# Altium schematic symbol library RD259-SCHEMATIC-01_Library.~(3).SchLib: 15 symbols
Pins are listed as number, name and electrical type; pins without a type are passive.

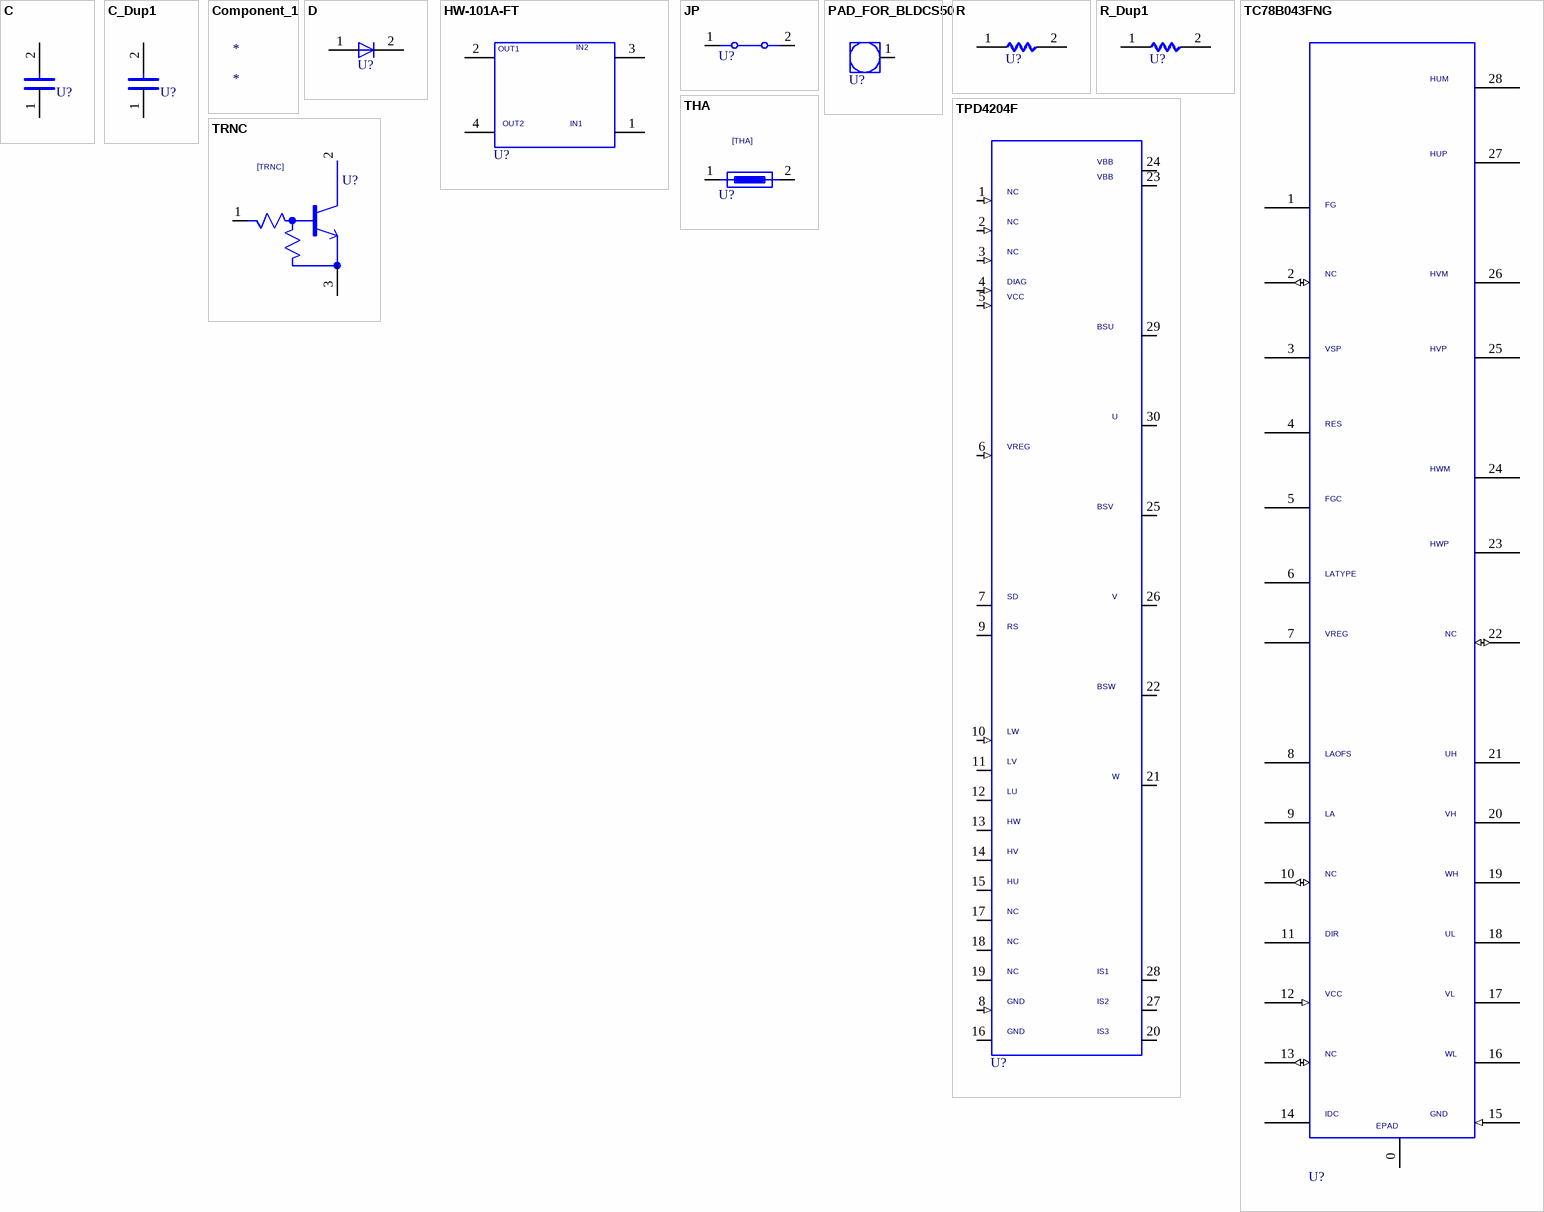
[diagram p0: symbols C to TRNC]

## C
designator U?  (value not drawn)
OriginalSymbolOrigin: (2540,7620); Altium-Right: 20; Altium-Bottom: 10
pins: 1, 2

## C_Dup1
designator U?, comment C  (value not drawn)
OriginalSymbolOrigin: (2540,7620); Altium-Right: 20; Altium-Bottom: 10
pins: 1, 2

## Component_1
designator *

## D
designator U?  (value not drawn)
SAVEAREA0: -225,-91,12804,7836; SAVECOUNT: 3; TIME: 14:49:55; UPDATEUSER: 19870035; UPDATETIME: 14:20:16; OriginalSymbolOrigin: (5080,5080); Altium-Right: 10; Altium-Bottom: 20
pins: 1 A, 2 C

## HW-101A-FT
designator U?  (value not drawn)
SAVEAREA0: -12224,-318,37706,25614; TIME: 11:47:14; UPDATEUSER: t5459927; UPDATETIME: 12:34:57; SAVECOUNT: 11; OriginalSymbolOrigin: (5080,17780); Altium-Right: 80; Altium-Bottom: 70
pins: 1, 2, 3, 4

## JP
designator U?  (value not drawn)
OriginalSymbolOrigin: (2540,5080); Altium-Right: 40; Altium-Bottom: 20
pins: 1, 2

## PAD_FOR_BLDCS50
designator U?  (value not drawn)
SAVEAREA0: -12224,-318,37706,25614; TIME: 11:47:14; UPDATEUSER: t5459927; UPDATETIME: 16:31:56; SAVECOUNT: 8; OriginalSymbolOrigin: (7620,17780); Altium-Right: 20
pins: 1

## R
designator U?  (value not drawn)
OriginalSymbolOrigin: (5080,5080); Altium-Right: 20
pins: 1, 2

## R_Dup1
designator U?, comment R  (value not drawn)
OriginalSymbolOrigin: (5080,5080); Altium-Right: 20
pins: 1, 2

## TC78B043FNG
designator U?  (value not drawn)
SAVEAREA0: -18325,-397,56528,38480; SAVECOUNT: 26; TIME: 12:23:18; UPDATEUSER: t5459927; UPDATETIME: 08:57:33; OriginalSymbolOrigin: (7620,190500); Altium-Right: 110; Altium-Bottom: 730
pins: 0, 1, 2 (io), 3, 4, 5, 6, 7, 8, 9, 10 (io), 11, 12 (in), 13 (io), 14, 15 (in), 16, 17, 18, 19, 20, 21, 22 (io), 23, 24, 25, 26, 27, 28

## THA
designator U?  (value not drawn)
SAVECOUNT: 3; SAVEAREA0: -562,-143,15615,10489; TIME: 16:37:29; UPDATEUSER: sato-yr; OriginalSymbolOrigin: (2540,5080); Altium-Right: 40; Altium-Bottom: 20
pins: 1, 2

## TPD4204F
designator U?  (value not drawn)
TIME: 16:32:01; UPDATEUSER: t5459927; UPDATETIME: 11:42:20; SAVECOUNT: 10; SAVEAREA0: -38352,-57023,57455,-16941; OriginalSymbolOrigin: (2540,154940); Altium-Right: 100; Altium-Bottom: 610
pins: 1 (in), 2 (in), 3 (in), 4 (in), 5 (in), 6 (in), 7, 8 (in), 9, 10 (in), 11, 12, 13, 14, 15, 16, 17, 18, 19, 20, 21, 22, 23, 24, 25, 26, 27, 28, 29, 30

## TRNC
designator U?  (value not drawn)
OriginalSymbolOrigin: (2540,22860); Altium-Right: 70
pins: 1 B, 2 C, 3 E

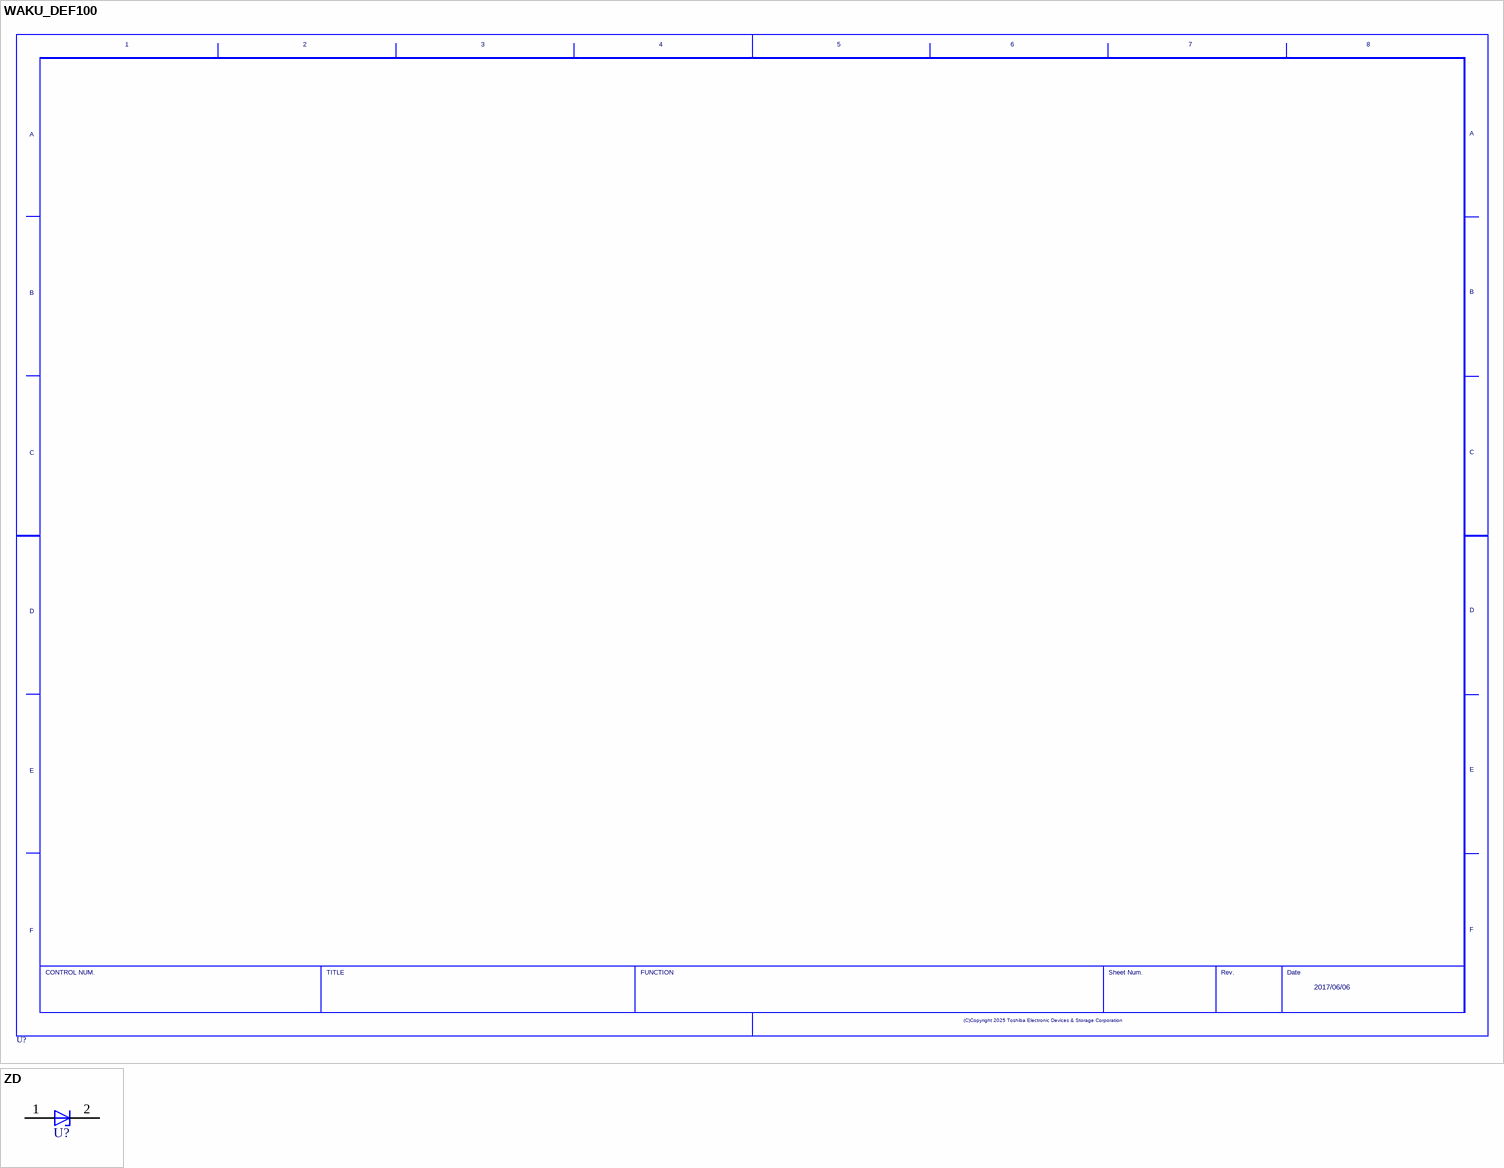
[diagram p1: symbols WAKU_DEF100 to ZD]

## WAKU_DEF100
designator U?  DATE: 2017/06/06  (hidden comment: WAKU_DEF100)
PLOTTIME: HH:MM; SAVEAREA0: -63393,-16950,474261,314592; TIME: 14:30:25; UPDATEUSER: t5459927; UPDATETIME: 16:48:10; SAVECOUNT: 4; OriginalSymbolOrigin: (10160,284480); Altium-Right: 1570; Altium-Bottom: 1070

## ZD
designator U?  (value not drawn)
SAVEAREA0: -4630,-153,17114,13055; TIME: 14:49:55; UPDATEUSER: fukuda-y; UPDATETIME: 08:18:42; SAVECOUNT: 6; OriginalSymbolOrigin: (5080,5080); Altium-Right: 10; Altium-Bottom: 20
pins: 1 A, 2 C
